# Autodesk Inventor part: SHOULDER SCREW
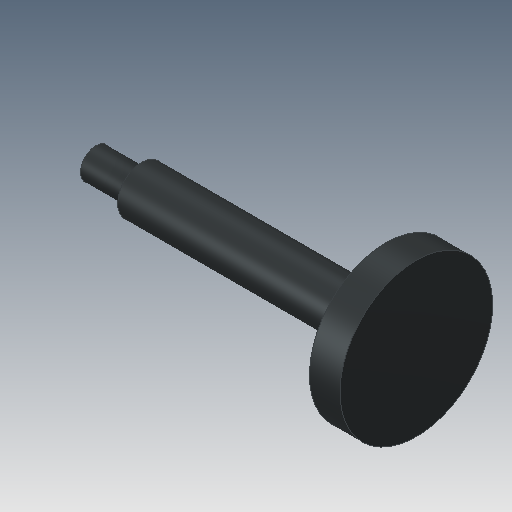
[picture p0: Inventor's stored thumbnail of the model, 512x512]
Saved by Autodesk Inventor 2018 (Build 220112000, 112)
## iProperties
Created: 2016-05
Part Number: SHOULDER SCREW
Material: Iron, Cast
Document SubType Name: Modeling
Designer: CADCIM
Density: 7.15 g/cm^3
Appearance: Iron Gray
Mass: 16.5435 g
Surface Area: 15.8336 cm^2
Volume: 2.31378 cm^3
Author: CADCIM
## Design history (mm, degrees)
sketch "Sketch1"
  geometry: L1 (0, 0)-(0, 2); L2 (0, 2)-(6, 2); L3 (6, 2)-(6, 3.125); L4 (6, 3.125)-(38, 3.125); L5 (38, 3.125)-(38, 10); L6 (38, 10)-(42, 10); L7 (42, 10)-(42, 0); L8 (42, 0)-(0, 0)
  constraints: 16 end point, 7 perpendicular, 1 vertical
  dimensions: "d0" = 4 diameter of L2 L8; "d1" = 6.25 diameter of L4 L8; "d2" = 20 diameter of L6 L8; "d3" = 32 distance between parallel lines of L5 L3; "d4" = 42 distance between parallel lines of L1 L7; "d5" = 4 distance of L5.end L6.end
revolve "Revolution1" sketch "Sketch1" stored, may be unused: angle "d6" = 90 deg
body "Solid1"
